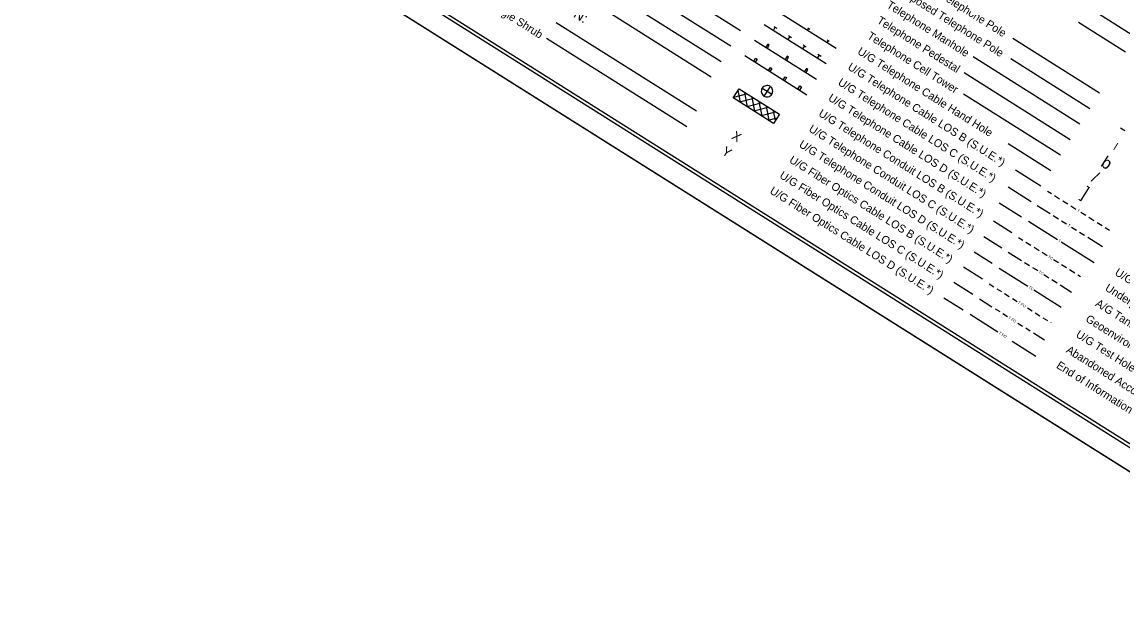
# Model space of a CAD drawing. Extents: x 2337092 to 2349158, y 800756 to 811724.
# Drawn here: x 2337092 to 2344308, y 800756 to 804511 of the extents above; entities that cross this region are included whole.
import ezdxf

# ---------------------------------------------------------------- set-up
doc = ezdxf.new("R2010")
doc.units = 0
for name, color, linetype in [('Sheet Cutting Line CELL', 7, 'Continuous'), ('Sheet Plot Border Inside CELL', 7, 'Continuous'), ('Sheet Plot Border Outside CELL', 7, 'Continuous'), ('Sheet Symbology CELL', 7, 'Continuous')]:
    doc.layers.add(name, color=color, linetype=linetype)

msp = doc.modelspace()

# ---------------------------------------------------------------- linework, layer by layer
at = {"layer": 'Sheet Cutting Line CELL'}
msp.add_line((2337091.6, 806137.8), (2345642.8, 800755.6), dxfattribs=at)
at = {"layer": 'Sheet Plot Border Inside CELL'}
msp.add_lwpolyline([(2337229.4, 806210.3), (2345691.7, 800884), (2349063.9, 806241.7), (2340601.5, 811568)], close=True, dxfattribs=at)
at = {"layer": 'Sheet Plot Border Outside CELL'}
msp.add_lwpolyline([(2337091.6, 806137.8), (2345642.8, 800755.6), (2349158.5, 806341.3), (2340607.3, 811723.5)], close=True, dxfattribs=at)
at = {"layer": 'Sheet Symbology CELL'}
for p, q in [((2341805.1, 804454.3), (2341275.4, 804787.6)), ((2341677.2, 804251.2), (2340953, 804707)), ((2341741.1, 804352.7), (2341211.5, 804686.1)), ((2341613.3, 804149.6), (2340889.1, 804605.5)), ((2342025.2, 804595.3), (2342431.4, 804339.6)), ((2344392.2, 804414.1), (2344070.3, 804616.7)), ((2341516.4, 803926.5), (2340596.7, 804505.4)), ((2344329.5, 804314.5), (2344021.3, 804508.4)), ((2342367.5, 804238), (2341961.2, 804493.7)), ((2342020.8, 804456.2), (2342033.4, 804476.3)), ((2342023.3, 804482.7), (2342043.6, 804469.9)), ((2342245.5, 804456.6), (2342253.5, 804469.3)), ((2342247.1, 804473.3), (2342259.8, 804465.3)), ((2341452.5, 803825), (2340532.7, 804403.9)), ((2341897.3, 804392.2), (2342303.6, 804136.5)), ((2342117.3, 804395.5), (2342129.9, 804415.6)), ((2342119.7, 804422), (2342140, 804409.2)), ((2342216.2, 804361.2), (2342236.5, 804348.5)), ((2342372.4, 804376.7), (2342380.4, 804389.4)), ((2342374.1, 804393.4), (2342386.8, 804385.4)), ((2344159.5, 804044.4), (2343591.4, 804402)), ((2341833.4, 804290.6), (2342239.6, 804034.9)), ((2342213.7, 804334.8), (2342226.4, 804354.8)), ((2342310.2, 804274.1), (2342322.9, 804294.1)), ((2342312.7, 804300.5), (2342333, 804287.7)), ((2344031.7, 803841.3), (2343331.6, 804281.9)), ((2344095.6, 803942.9), (2343577.3, 804269.1)), ((2343967.8, 803739.8), (2343271.3, 804178.2)), ((2341757.7, 804013.2), (2341795.1, 804072.7)), ((2341795.1, 804072.7), (2342059.7, 803906.1)), ((2341947, 804077.2), (2341978.8, 804057.2)), ((2341998.8, 804089), (2341978.8, 804057.2)), ((2342022.3, 803846.7), (2341757.7, 804013.2)), ((2341761.4, 804019.1), (2341845.2, 804041.2)), ((2341804.7, 803983.7), (2341789.4, 804063.5)), ((2341793.2, 804069.6), (2341797.9, 804070.9)), ((2341799.1, 803987.2), (2341892.4, 804011.5)), ((2341851.9, 803954), (2341833.5, 804048.5)), ((2341898.9, 803924.4), (2341880.7, 804018.8)), ((2341978.8, 804057.2), (2341958.8, 804025.5)), ((2341978.8, 804057.2), (2342010.5, 804037.2)), ((2343903.8, 803638.2), (2343268, 804038.4)), ((2341846.1, 803957.6), (2341939.6, 803981.7)), ((2341893.3, 803927.9), (2341986.6, 803952.2)), ((2341946.1, 803894.7), (2341927.7, 803989.2)), ((2341993.4, 803865), (2341974.6, 803959.7)), ((2342034.3, 803865.8), (2342021.9, 803930)), ((2341940.5, 803898.2), (2342033.5, 803922.6)), ((2341987.5, 803868.6), (2342045.6, 803883.8)), ((2342059.7, 803906.1), (2342022.3, 803846.7)), ((2344325.6, 803798), (2344297, 803816)), ((2343839.9, 803536.7), (2343560.4, 803712.6)), ((2343776, 803435.1), (2343609.5, 803539.9)), ((2343712.1, 803333.5), (2343561.6, 803428.2)), ((2343819.2, 803402.2), (2343844.7, 803386.2)), ((2343865, 803373.4), (2343898, 803352.6)), ((2343648.2, 803232), (2343501.6, 803324.2)), ((2343751.5, 803308.7), (2343836.7, 803255.1)), ((2343918.4, 803339.8), (2343951.4, 803319.1)), ((2343971.7, 803306.3), (2344004.7, 803285.5)), ((2343584.2, 803130.4), (2343465.1, 803205.4)), ((2343857, 803242.3), (2343890, 803221.6)), ((2343910.3, 803208.8), (2343943.3, 803188)), ((2344037.2, 803265), (2344070.2, 803244.3)), ((2344090.5, 803231.5), (2344123.5, 803210.7)), ((2343695, 803205), (2343883.6, 803086.3)), ((2343975.8, 803167.5), (2344008.8, 803146.8)), ((2344029.1, 803134), (2344062.1, 803113.2)), ((2344143.8, 803197.9), (2344176.8, 803177.2)), ((2344197.1, 803164.4), (2344225.4, 803146.5)), ((2343520.3, 803028.9), (2343401.2, 803103.9)), ((2343628.6, 803099.4), (2343657, 803081.6)), ((2343677.3, 803068.8), (2343710.3, 803048)), ((2343908.9, 803070.3), (2344124.1, 802934.9)), ((2344082.4, 803100.4), (2344179.1, 803039.6)), ((2343456.4, 802927.3), (2343337.2, 803002.3)), ((2343561.2, 803003.1), (2343647.8, 802948.6)), ((2343730.6, 803035.2), (2343763.6, 803014.5)), ((2343783.9, 803001.7), (2343817, 802980.9)), ((2343668.1, 802935.9), (2343701.1, 802915.1)), ((2343857.6, 802955.3), (2343890.6, 802934.6)), ((2343910.9, 802921.8), (2343943.9, 802901)), ((2343392.5, 802825.7), (2343267.4, 802904.5)), ((2343502, 802898.3), (2343690.3, 802779.7)), ((2343721.4, 802902.3), (2343754.4, 802881.5)), ((2343795, 802856), (2343828, 802835.2)), ((2343964.2, 802888.2), (2343997.2, 802867.4)), ((2344017.5, 802854.7), (2344034.9, 802843.8)), ((2343328.5, 802724.2), (2343203.5, 802802.9)), ((2343436.8, 802794.7), (2343466.5, 802776.1)), ((2343848.3, 802822.4), (2343881.3, 802801.6)), ((2343901.7, 802788.8), (2343977.2, 802741.3)), ((2343264.6, 802622.6), (2343139.6, 802701.3)), ((2343486.8, 802763.3), (2343517.3, 802744.1)), ((2343537.6, 802731.3), (2343568, 802712.2)), ((2343728.4, 802755.7), (2343908.2, 802642.6)), ((2343373.4, 802696), (2343454.7, 802644.8)), ((2343475, 802632), (2343505.5, 802612.8)), ((2343588.3, 802699.4), (2343618.8, 802680.2)), ((2343687.4, 802637), (2343717.8, 802617.9)), ((2343311.4, 802595.5), (2343493.6, 802480.8)), ((2343525.8, 802600), (2343556.3, 802580.8)), ((2343738.1, 802605.1), (2343768.6, 802585.9)), ((2343788.9, 802573.1), (2343819.4, 802553.9)), ((2343624.8, 802537.7), (2343655.3, 802518.5)), ((2343675.6, 802505.7), (2343706.1, 802486.6)), ((2343839.7, 802541.2), (2343843.1, 802539)), ((2343586.3, 802419.8), (2343741.8, 802321.9)), ((2343726.4, 802473.8), (2343799.1, 802428))]:
    msp.add_line(p, q, dxfattribs=at)
for points in [[(2348992.3, 806268.7), (2341375.4, 811062.8), (2338022.8, 805736.2), (2345639.6, 800942.1)], [(2341970.8, 804345.9), (2341981, 804339.5), (2341993.8, 804359.8), (2341983.6, 804366.2)], [(2341904.4, 804274.3), (2341914.5, 804267.9), (2341901.8, 804247.6), (2341891.6, 804254)], [(2342097.8, 804266), (2342107.9, 804259.6), (2342120.7, 804279.9), (2342110.6, 804286.3)], [(2342000.9, 804213.5), (2342011, 804207.2), (2341998.2, 804186.8), (2341988.1, 804193.2)], [(2342097.4, 804152.8), (2342107.5, 804146.4), (2342094.7, 804126.1), (2342084.6, 804132.5)], [(2342224.7, 804186.1), (2342234.9, 804179.7), (2342247.7, 804200), (2342237.5, 804206.4)], [(2342193.8, 804092.1), (2342204, 804085.7), (2342191.2, 804065.4), (2342181, 804071.8)]]:
    msp.add_lwpolyline(points, close=True, dxfattribs=at)
for start, end in [(147.80783, 237.81236), (57.80783, 147.81236), (327.80783, 57.81236), (237.80783, 327.81236)]:
    msp.add_arc((2341978.8, 804057.2), 37.5, start, end, dxfattribs=at)

# ---------------------------------------------------------------- texts
for s, height, p in [('VEGETATION:', 66, (2340276.6, 804816.4)), ('Existing Telephone Pole', 52.5, (2342887.2, 804813.1)), ('Proposed Telephone Pole', 52.5, (2342823.2, 804711.6)), ('Single Shrub', 52.5, (2340147.4, 804614.3)), ('Telephone Manhole', 52.5, (2342759.3, 804610)), ('Telephone Pedestal', 52.5, (2342695.4, 804508.4)), ('Telephone Cell Tower', 52.5, (2342631.5, 804406.8)), ('U/G Telephone Cable Hand Hole', 52.5, (2342567.6, 804305.3)), ('U/G Telephone Cable LOS B (S.U.E.*)', 52.5, (2342503.7, 804203.7)), ('U/G Telephone Cable LOS C (S.U.E.*)', 52.5, (2342439.8, 804102.2)), ('U/G Telephone Cable LOS D (S.U.E.*)', 52.5, (2342375.9, 804000.6)), ('U/G Telephone Conduit LOS B (S.U.E.*)', 52.5, (2342311.9, 803899)), ('X', 60, (2341741.1, 803749.7)), ('U/G Telephone Conduit LOS C (S.U.E.*)', 52.5, (2342248, 803797.5)), ('U/G Telephone Conduit LOS D (S.U.E.*)', 52.5, (2342184.1, 803695.9)), ('l', 49.5, (2344246.4, 803676.9)), ('Y', 60, (2341677.2, 803648.1)), ('U/G Fiber Optics Cable LOS B (S.U.E.*)', 52.5, (2342120.2, 803594.4)), ('b', 79.2, (2344162, 803570.7)), ('U/G Fiber Optics Cable LOS C (S.U.E.*)', 52.5, (2342056.2, 803492.8)), ('/', 75, (2344101, 803469.8)), ('U/G Fiber Optics Cable LOS D (S.U.E.*)', 52.5, (2341992.3, 803391.3)), (']', 81, (2344032.9, 803367.3)), ('T', 18, (2344011.3, 803270.7)), ('T', 18, (2343949.9, 803173.2)), ('T', 18, (2343886.6, 803073.7)), ('TC', 18, (2343820.3, 802968.2)), ('TC', 18, (2343757.7, 802868.8)), ('U/G Tank; Water, Gas, Oil', 52.5, (2344255.8, 802856.6)), ('TC', 18, (2343692.4, 802767.8)), ('Underground Storage Tank, Approx. Loc.', 52.5, (2344191.9, 802755.1)), ('T FO', 18, (2343621.6, 802667.8)), ('A/G Tank; Water, Gas, Oil', 52.5, (2344128, 802653.5)), ('T FO', 18, (2343559.1, 802568.4)), ('Geoenvironmental Boring', 52.5, (2344064.1, 802551.9)), ('U/G Test Hole LOS A (S.U.E.*)', 52.5, (2344000.1, 802450.4)), ('T FO', 18, (2343496.4, 802468.4)), ('Abandoned According to Utility Records', 52.5, (2343936.2, 802348.8)), ('End of Information', 52.5, (2343872.3, 802247.3))]:
    msp.add_text(s, height=height, rotation=327.81344, dxfattribs=at).set_placement(p)

doc.saveas('drawing.dxf')
